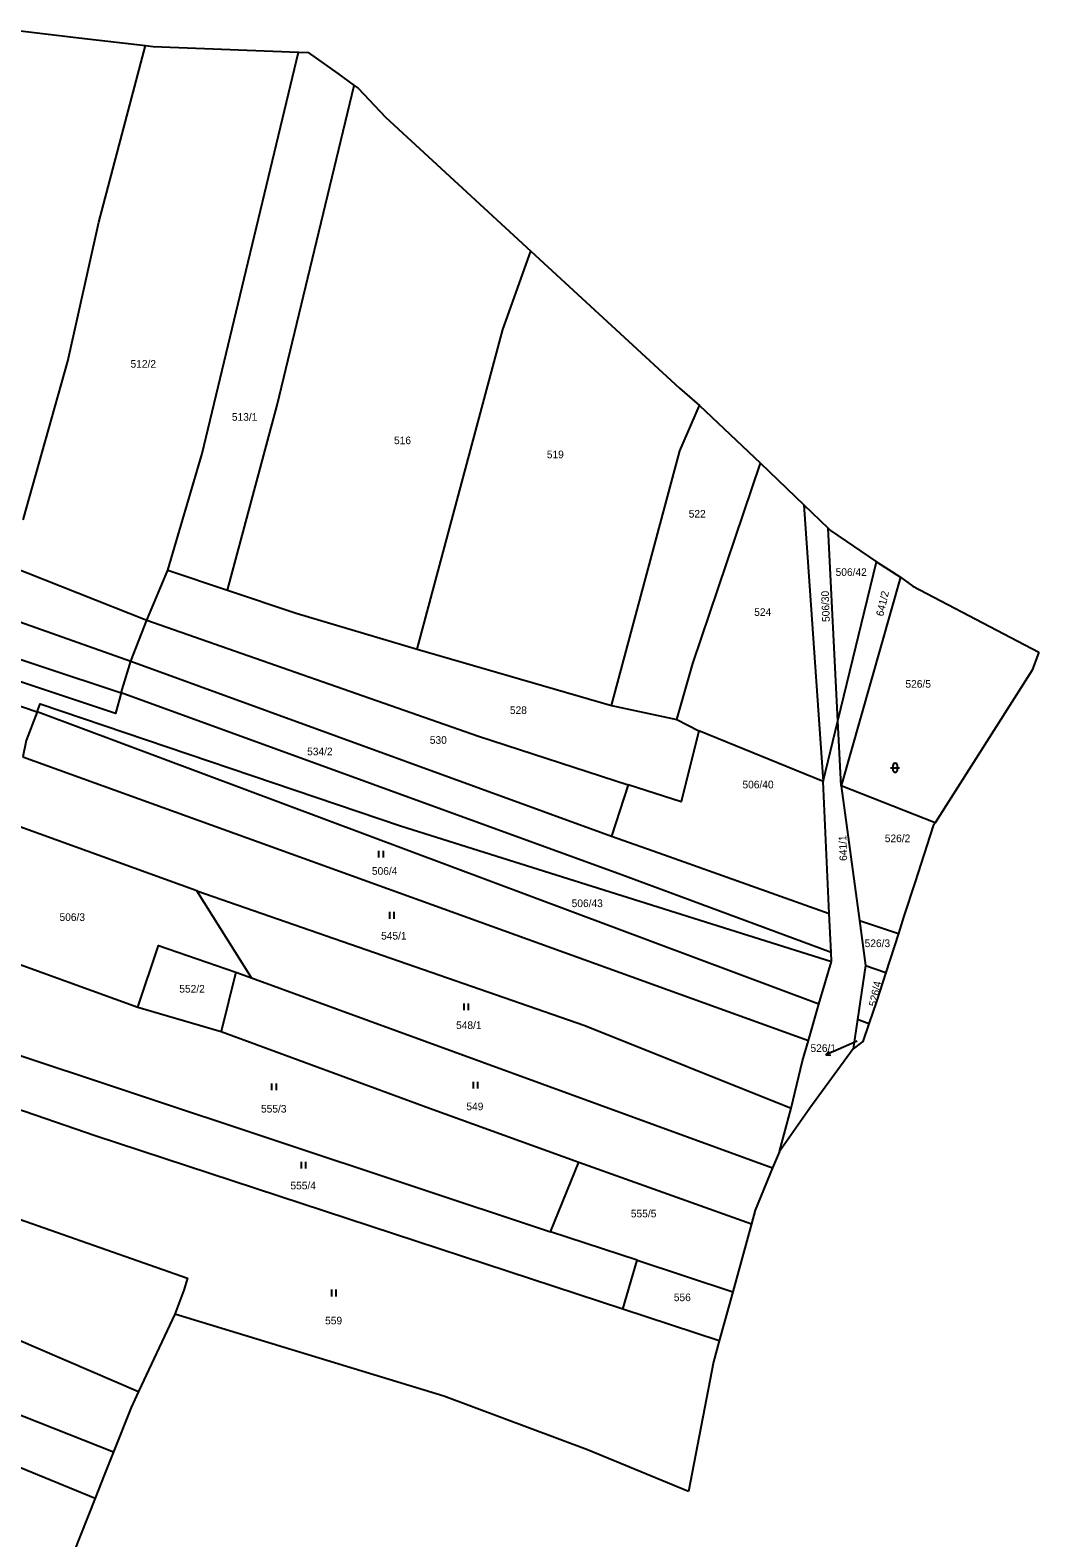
# Model space of a CAD drawing. Extents: x -744566 to -741843, y -1128407 to -1126744.
# Drawn here: x -742068.2 to -741843.1, y -1127136.3 to -1126800.1 of the extents above; entities that cross this region are included whole.
import ezdxf

# ---------------------------------------------------------------- set-up
doc = ezdxf.new("R2010")
doc.units = 0
for name, color, linetype in [('Hranice parcel', 7, 'Continuous'), ('Parcelní čísla', 7, 'Continuous'), ('Pop  PČ popisy', 7, 'Continuous'), ('Značky kultur', 7, 'Continuous')]:
    doc.layers.add(name, color=color, linetype=linetype)

msp = doc.modelspace()

# ---------------------------------------------------------------- linework, layer by layer
at = {"layer": 'Hranice parcel'}
for p, q in [((-741999.58, -1126809.75), (-741995.88, -1126812.38)), ((-741918.85, -1126883.8), (-741905.2, -1126896.65)), ((-741905.2, -1126896.65), (-741895.54, -1126905.95)), ((-741895.54, -1126905.95), (-741890.11, -1126911.17)), ((-741895.54, -1126905.95), (-741891.25, -1126967.65)), ((-741890.11, -1126911.17), (-741889.64, -1126911.62)), ((-741887.96, -1126954.12), (-741890.11, -1126911.17)), ((-741889.64, -1126911.62), (-741879.33, -1126918.65)), ((-742170.7, -1126917.2), (-742066.64, -1126952.09)), ((-742072.95, -1126919.43), (-742042.16, -1126931.63)), ((-742042.16, -1126931.63), (-742037.51, -1126920.53)), ((-742037.51, -1126920.53), (-742024.13, -1126924.93)), ((-741887.96, -1126954.12), (-741879.33, -1126918.65)), ((-741879.33, -1126918.65), (-741874.03, -1126922.09)), ((-741874.03, -1126922.09), (-741887.23, -1126968.62)), ((-741874.03, -1126922.09), (-741871.22, -1126924.06)), ((-741871.22, -1126924.06), (-741843.12, -1126938.81)), ((-742045.77, -1126940.83), (-742042.16, -1126931.63)), ((-741981.81, -1126938.12), (-741938.49, -1126950.65)), ((-742047.88, -1126947.84), (-742045.77, -1126940.83)), ((-742045.77, -1126940.83), (-741938.47, -1126979.84)), ((-741843.12, -1126938.81), (-741844.65, -1126942.82)), ((-741844.65, -1126942.82), (-741866.25, -1126976.82)), ((-741938.49, -1126950.65), (-741923.91, -1126953.81)), ((-741892.18, -1127017.32), (-742066.64, -1126952.09)), ((-741923.91, -1126953.81), (-741919, -1126956.3)), ((-741891.25, -1126967.65), (-741887.96, -1126954.12)), ((-741887.23, -1126968.62), (-741887.96, -1126954.12)), ((-741891.25, -1126967.65), (-741919, -1126956.3)), ((-742069.84, -1126962.11), (-741894.54, -1127025.39)), ((-741934.76, -1126968.35), (-741938.47, -1126979.84)), ((-741889.89, -1126997.11), (-741891.25, -1126967.65)), ((-741887.23, -1126968.62), (-741883.16, -1126998.66)), ((-741866.25, -1126976.82), (-741887.23, -1126968.62)), ((-742031.04, -1126992.02), (-742072.97, -1126976.88)), ((-742018.83, -1127011.41), (-742031.04, -1126992.02)), ((-741889.49, -1127005.77), (-741889.89, -1126997.11)), ((-741883.16, -1126998.66), (-741874.46, -1127001.53)), ((-741883.16, -1126998.66), (-741881.8, -1127008.68)), ((-741873.22, -1126997.69), (-741874.46, -1127001.53)), ((-741874.46, -1127001.53), (-741877.28, -1127010.23)), ((-742080.25, -1127004.92), (-742044.21, -1127017.99)), ((-741892.18, -1127017.32), (-741889.4, -1127007.8)), ((-741889.4, -1127007.8), (-741889.49, -1127005.77)), ((-741881.8, -1127008.68), (-741883.57, -1127020.71)), ((-741881.8, -1127008.68), (-741877.28, -1127010.23)), ((-742022.32, -1127010.2), (-742025.58, -1127023.42)), ((-742022.32, -1127010.2), (-742018.83, -1127011.41)), ((-742018.83, -1127011.41), (-741902.53, -1127053.84)), ((-742044.21, -1127017.99), (-742025.58, -1127023.42)), ((-741894.54, -1127025.39), (-741892.18, -1127017.32)), ((-741883.57, -1127020.71), (-741884.54, -1127027.28)), ((-741881.07, -1127021.7), (-741883.57, -1127020.71)), ((-742085.96, -1127023.63), (-741952.12, -1127068.07)), ((-741901.01, -1127050.15), (-741898.4, -1127040.53)), ((-741952.12, -1127068.07), (-741945.8, -1127052.51)), ((-741945.8, -1127052.51), (-741907.25, -1127066.27)), ((-741901.01, -1127050.15), (-741902.53, -1127053.84)), ((-741932.79, -1127074.43), (-741952.12, -1127068.07)), ((-741907.25, -1127066.27), (-741911.44, -1127081.45)), ((-741935.95, -1127085.33), (-741932.79, -1127074.43)), ((-741932.79, -1127074.43), (-741911.44, -1127081.45)), ((-742033.9, -1127081.06), (-742035.92, -1127086.47)), ((-741911.44, -1127081.45), (-741914.45, -1127092.38)), ((-741914.45, -1127092.38), (-741935.95, -1127085.33)), ((-742035.92, -1127086.47), (-742044, -1127103.72)), ((-741914.45, -1127092.38), (-741915.73, -1127097.04)), ((-741915.73, -1127097.04), (-741921.32, -1127125.97)), ((-742049.6, -1127117.15), (-742051.66, -1127122.32)), ((-741921.32, -1127125.97), (-741943.86, -1127116.69)), ((-742051.66, -1127122.32), (-742053.72, -1127127.51)), ((-742053.72, -1127127.51), (-742062.93, -1127150.64))]:
    msp.add_line(p, q, dxfattribs=at)
for points in [[(-742071.61, -1126800.06), (-742057.34, -1126801.74), (-742042.45, -1126803.48)], [(-742069.77, -1126909.24), (-742059.79, -1126873.9), (-742052.88, -1126842.88), (-742042.45, -1126803.48)], [(-742042.45, -1126803.48), (-742040.75, -1126803.68), (-742008.33, -1126804.96)], [(-742037.51, -1126920.53), (-742029.79, -1126894.48), (-742008.33, -1126804.96)], [(-742008.33, -1126804.96), (-742006.2, -1126805.04), (-741999.58, -1126809.75)], [(-742434.93, -1126808.05), (-742383.95, -1126826.97), (-742163.59, -1126899.11), (-742045.77, -1126940.83)], [(-742024.13, -1126924.93), (-742013.07, -1126883.73), (-741995.88, -1126812.38)], [(-741995.88, -1126812.38), (-741995.03, -1126812.98), (-741988.91, -1126819.48), (-741956.5, -1126849.33)], [(-742438.82, -1126815.98), (-742394.95, -1126832.23), (-742364.36, -1126842.59), (-742205.97, -1126895.42), (-742047.88, -1126947.84)], [(-742047.88, -1126947.84), (-742049.19, -1126952.47), (-742228, -1126892.81), (-742365.77, -1126848.2), (-742441.29, -1126821.14)], [(-741981.81, -1126938.12), (-741962.74, -1126866.8), (-741956.5, -1126849.33)], [(-741956.5, -1126849.33), (-741923.28, -1126879.92), (-741918.85, -1126883.8)], [(-741938.49, -1126950.65), (-741923.2, -1126893.92), (-741918.85, -1126883.8)], [(-741923.91, -1126953.81), (-741920.35, -1126941.29), (-741905.2, -1126896.65)], [(-742024.13, -1126924.93), (-742008.81, -1126930.11), (-741981.81, -1126938.12)], [(-742042.16, -1126931.63), (-741968.16, -1126957.55), (-741934.76, -1126968.35)], [(-742504.35, -1126941.71), (-742474.75, -1126953.67), (-742378.88, -1126988.04), (-742204.08, -1127046.96), (-742100.58, -1127080.82), (-742076.73, -1127089.67), (-742044, -1127103.72)], [(-741889.49, -1127005.77), (-741935.44, -1126988.77), (-742047.88, -1126947.84)], [(-742066.64, -1126952.09), (-742065.96, -1126950.33), (-741985.58, -1126977.5), (-741889.4, -1127007.8)], [(-742066.64, -1126952.09), (-742069.11, -1126958.48), (-742069.84, -1126962.11)], [(-742512.02, -1126957.27), (-742426.6, -1126987.75), (-742322.02, -1127023.9), (-742152.02, -1127080.85), (-742092.77, -1127100.11), (-742049.6, -1127117.15)], [(-741919, -1126956.3), (-741922.92, -1126972.18), (-741934.76, -1126968.35)], [(-742516.09, -1126965.6), (-742463.84, -1126985.43), (-742374.91, -1127016.27), (-742226.88, -1127065.31), (-742153.9, -1127090.43), (-742091.98, -1127111.83), (-742053.72, -1127127.51)], [(-741866.25, -1126976.82), (-741866.67, -1126977.49), (-741870.81, -1126990.26), (-741873.22, -1126997.69)], [(-741938.47, -1126979.84), (-741926.65, -1126983.96), (-741889.89, -1126997.11)], [(-742031.04, -1126992.02), (-741944.43, -1127022.07), (-741898.4, -1127040.53)], [(-742044.21, -1127017.99), (-742039.6, -1127004.23), (-742022.32, -1127010.2)], [(-741877.28, -1127010.23), (-741879.38, -1127016.69), (-741881.07, -1127021.7)], [(-741881.07, -1127021.7), (-741882.39, -1127025.62), (-741884.54, -1127027.28)], [(-742025.58, -1127023.42), (-741979.11, -1127040.48), (-741945.8, -1127052.51)], [(-741898.4, -1127040.53), (-741895.88, -1127029.96), (-741894.54, -1127025.39)], [(-741884.54, -1127027.28), (-741894.2, -1127040.5), (-741901.01, -1127050.15)], [(-741935.95, -1127085.33), (-742053.68, -1127046.69), (-742080.56, -1127037.47)], [(-741902.53, -1127053.84), (-741906.42, -1127063.26), (-741907.25, -1127066.27)], [(-742091.61, -1127057.86), (-742033.08, -1127078.43), (-742033.9, -1127081.06)], [(-741943.86, -1127116.69), (-741975.91, -1127104.72), (-742035.92, -1127086.47)], [(-742044, -1127103.72), (-742045.65, -1127107.23), (-742049.6, -1127117.15)]]:
    msp.add_lwpolyline(points, dxfattribs=at)
at = {"layer": 'Pop  PČ popisy'}
for p, q in [((-741883.65, -1127025.54), (-741887.88, -1127027.39)), ((-741887.88, -1127027.39), (-741890.622, -1127028.611)), ((-741890.622, -1127028.611), (-741889.91, -1127027.746)), ((-741890.622, -1127028.611), (-741889.503, -1127028.661))]:
    msp.add_line(p, q, dxfattribs=at)
at = {"layer": 'Značky kultur'}
for p, q in [((-741876.191, -1126964.581), (-741874.189, -1126964.581)), ((-741875.691, -1126964.081), (-741875.691, -1126965.082)), ((-741874.689, -1126965.082), (-741874.689, -1126964.081)), ((-741990.371, -1126984.62), (-741990.371, -1126983.12)), ((-741989.37, -1126984.62), (-741989.37, -1126983.12)), ((-741987.971, -1126998.24), (-741987.971, -1126996.74)), ((-741986.97, -1126998.24), (-741986.97, -1126996.74)), ((-741971.371, -1127018.66), (-741971.371, -1127017.16)), ((-741970.37, -1127018.66), (-741970.37, -1127017.16)), ((-742014.261, -1127036.48), (-742014.261, -1127034.98)), ((-742013.26, -1127036.48), (-742013.26, -1127034.98)), ((-741969.301, -1127036.13), (-741969.301, -1127034.63)), ((-741968.3, -1127036.13), (-741968.3, -1127034.63)), ((-742007.691, -1127053.96), (-742007.691, -1127052.46)), ((-742006.69, -1127053.96), (-742006.69, -1127052.46)), ((-742000.921, -1127082.47), (-742000.921, -1127080.97)), ((-741999.92, -1127082.47), (-741999.92, -1127080.97))]:
    msp.add_line(p, q, dxfattribs=at)
for centre, start, end in [((-741875.19, -1126964.081), 0, 180), ((-741875.19, -1126965.081), 180, 359.98789)]:
    msp.add_arc(centre, 0.5, start, end, dxfattribs=at)

# ---------------------------------------------------------------- texts
at = {"layer": 'Parcelní čísla'}
for s, p in [('512/2', (-742045.8, -1126875.34)), ('513/1', (-742023.19, -1126887.18)), ('516', (-741987.01, -1126892.4)), ('519', (-741952.91, -1126895.54)), ('522', (-741921.25, -1126908.77)), ('506/42', (-741888.47, -1126921.78)), ('524', (-741906.64, -1126930.7)), ('526/5', (-741872.89, -1126946.72)), ('528', (-741961.15, -1126952.58)), ('530', (-741979.02, -1126959.23)), ('534/2', (-742006.4, -1126961.79)), ('506/40', (-741909.26, -1126969.16)), ('526/2', (-741877.5, -1126981.17)), ('506/4', (-741991.94, -1126988.44)), ('506/43', (-741947.37, -1126995.65)), ('506/3', (-742061.65, -1126998.74)), ('545/1', (-741989.893, -1127002.9)), ('526/3', (-741882, -1127004.57)), ('552/2', (-742034.92, -1127014.72)), ('548/1', (-741973.16, -1127022.84)), ('526/1', (-741894.076, -1127027.96)), ('555/3', (-742016.69, -1127041.48)), ('549', (-741970.86, -1127040.96)), ('555/4', (-742010.12, -1127058.61)), ('555/5', (-741934.16, -1127064.85)), ('556', (-741924.57, -1127083.54)), ('559', (-742002.384, -1127088.72))]:
    msp.add_text(s, height=1.7, dxfattribs=at).set_placement(p)
for s, rotation, p in [('506/30', 92, (-741889.76, -1126932.03)), ('641/2', 77, (-741877.831, -1126930.911)), ('641/1', 92, (-741885.89, -1126985.31)), ('526/4', 78, (-741879.418, -1127017.946))]:
    msp.add_text(s, height=1.7, rotation=rotation, dxfattribs=at).set_placement(p)

doc.saveas('drawing.dxf')
